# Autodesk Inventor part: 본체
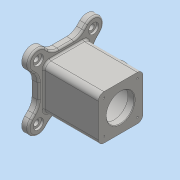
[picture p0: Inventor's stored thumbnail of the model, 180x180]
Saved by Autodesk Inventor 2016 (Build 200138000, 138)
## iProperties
Created: 2019-11
Part Number: 본체
Material: 일반
Document SubType Name: Modeling
Designer: user
Density: 1 g/cm^3
Appearance: 기본값
Author: user
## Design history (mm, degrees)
sketch "스케치1"
  geometry: L1 (49, 49)-(-49, 49); L2 (-49, 49)-(-49, -49); L3 (-49, -49)-(49, -49); L4 (49, -49)-(49, 49); L5 (49, 49)-(-49, -49); L6 (-49, 49)-(49, -49); L7 (-49.497, 49.497)-(49.497, -49.497); L8 (-62.225, 36.77)-(36.77, -62.225); L9 (62.225, -36.77)-(-36.77, 62.225); L10 (-49.497, -49.497)-(49.497, 49.497); L11 (-36.77, -62.225)-(62.225, 36.77); L12 (36.77, 62.225)-(-62.225, -36.77); A1 r 18 centre (-49.497, 49.497) between (-36.77, 62.225) and (-62.225, 36.77); A2 r 18 centre (49.497, -49.497) between (36.77, -62.225) and (62.225, -36.77); A3 r 18 centre (-49.497, -49.497) between (-62.225, -36.77) and (-36.77, -62.225); A4 r 18 centre (49.497, 49.497) between (62.225, 36.77) and (36.77, 62.225); A5 r 70 centre (0, 0) between (49.497, -49.497) and (-49.497, -49.497); 1 further point
  constraints: 28 end point, 10 point on circle, 8 tangent, 5 centre point, 4 midpoint, 4 parallel, 2 point on line, 1 coincident, 1 horizontal, 1 perpendicular
  dimensions: "d0" = 98 distance of L3.end L2.end; "d1" = 98 distance of L2.end L1.end; "d2" = 36 diameter of A2; "d3" = 36 diameter of A4; "d4" = 70 radius of A5
extrude "돌출1" new body sketch "스케치1" distance "d5" = 12; taper "d6" = 0 deg
sketch "스케치2"
  geometry: L1 (-40, 40)-(40, 40); L2 (40, 40)-(40, -40); L3 (40, -40)-(-40, -40); L4 (-40, -40)-(-40, 40); L5 (-40, 40)-(40, -40); L6 (40, 40)-(-40, -40); 1 further point
  constraints: 12 end point, 2 midpoint, 2 parallel, 1 horizontal, 1 perpendicular
  dimensions: "d7" = 80 distance of L2.end L3.end; "d8" = 80 distance of L1.end L2.end
extrude "돌출2" join sketch "스케치2" distance "d9" = 98; taper "d10" = 0 deg
sketch "스케치3"
  geometry: L1 (-30, 30)-(30, 30); L2 (30, 30)-(30, -30); L3 (30, -30)-(-30, -30); L4 (-30, -30)-(-30, 30); L5 (-30, 30)-(30, -30); L6 (30, 30)-(-30, -30); 5 further points
  constraints: 12 end point, 4 coincident, 2 midpoint, 2 parallel, 1 horizontal, 1 perpendicular
  dimensions: "d11" = 60 distance of L2.end L3.end; "d12" = 60 distance of L1.end L2.end
hole "구멍1" sketch "스케치3" at (-30, 30), (-30, -30), (30, -30), (30, 30) diameter "d13" = 3.242; stored, may be unused: countersink angle "d17" = 90 deg, drill point angle "d19" = 118 deg; dims "d14" = 8, "d15" = 4, "d16" = 2, "d18" = 10
node "작업 평면2"
  node "작업 평면1"
sketch "스케치5"
  geometry: A1 r 18 centre (-49.497, 49.497) between (-36.77, 62.225) and (-62.225, 36.77) reference; A2 r 18 centre (49.497, 49.497) between (62.225, 36.77) and (36.77, 62.225) reference; A3 r 18 centre (49.497, -49.497) between (36.77, -62.225) and (62.225, -36.77) reference; A4 r 18 centre (-49.497, -49.497) between (-62.225, -36.77) and (-36.77, -62.225) reference; 5 further points
  constraints: 4 coincident
hole "구멍3" sketch "스케치5" at (-49.497, 49.497), (49.497, 49.497), (49.497, -49.497), (-49.497, -49.497) diameter "d29" = 10; stored, may be unused: countersink angle "d33" = 90 deg, drill point angle "d35" = 118 deg; dims "d30" = 8, "d31" = 18, "d32" = 4, "d34" = 50
node "작업 평면3"
sketch "스케치8"
  geometry: L1 (-12, 67.497)-(-12, 36.77) reference; L2 (-12, -40)-(-110, -40) reference; C1 r 20 at (-61, 0); 2 further points
  constraints: 1 centre point
  dimensions: "d40" = 40 diameter of C1; "d41" = 49 distance from line of L1 C1.centre; "d42" = 40 distance from line of L2 C1.centre
extrude "돌출3" join sketch "스케치8" stored distance "d43" = 98; taper "d44" = 0 deg
sketch "스케치9"
  geometry: C1 r 25 at (0, 0); 1 further point
  constraints: 1 centre point, 1 coincident
  dimensions: "d45" = 50 diameter of C1
extrude "돌출4" cut sketch "스케치9" distance "d46" = 12; taper "d47" = 0 deg
sketch "스케치10"
  geometry: C1 r 35 at (0, 0); 1 further point
  constraints: 1 centre point, 1 coincident
  dimensions: "d48" = 70 diameter of C1
extrude "돌출5" cut sketch "스케치10" distance "d49" = 86; taper "d50" = 0 deg
sketch "스케치11"
  geometry: C1 r 25 at (0, 0); 1 further point
  constraints: 1 centre point, 1 coincident
  dimensions: "d51" = 50 diameter of C1
extrude "돌출6" cut sketch "스케치11" distance "d52" = 12; taper "d53" = 0 deg
sketch "스케치12"
  geometry: C1 r 20 at (0, 0) reference; 2 further points
  constraints: 1 coincident
hole "구멍4" sketch "스케치12" at (0, 0) diameter "d54" = 25; stored, may be unused: countersink angle "d58" = 90 deg, drill point angle "d60" = 118 deg; dims "d55" = 8, "d56" = 30, "d57" = 8, "d59" = 50
fillet "모깎기1" dims "d61" = 25
fillet "모깎기2" dims "d62" = 10
fillet "모깎기3" dims "d63" = 3
fillet "모깎기4" dims "d64" = 3
fillet "모깎기5" dims "d65" = 3
fillet "모깎기6" dims "d66" = 3
chamfer "모따기1" distance "d67" = 1; stored, may be unused: second distance "d68" = 2, angle "d69" = 45 deg
sketch "스케치13"
  geometry: L1 (0, 60)-(0, 0) reference; L2 (-98, 16.811)-(-98, 43.189) reference; 3 further points
  constraints: 1 horizontal alignment, 1 midpoint, 1 other
  dimensions: "d70" = 10 distance from line of L1 point (-10, 30)
feature "엠보싱1" sketch "스케치13" dims "d0" = 98, "d1" = 98, "d2" = 36, "d3" = 36, "d4" = 70, "d71" = 0.5, "d72" = 0
node "솔리드1"
mirror "대칭1"
other parameters: "d20" = 55, "d21" = -12, "d39" = 55
